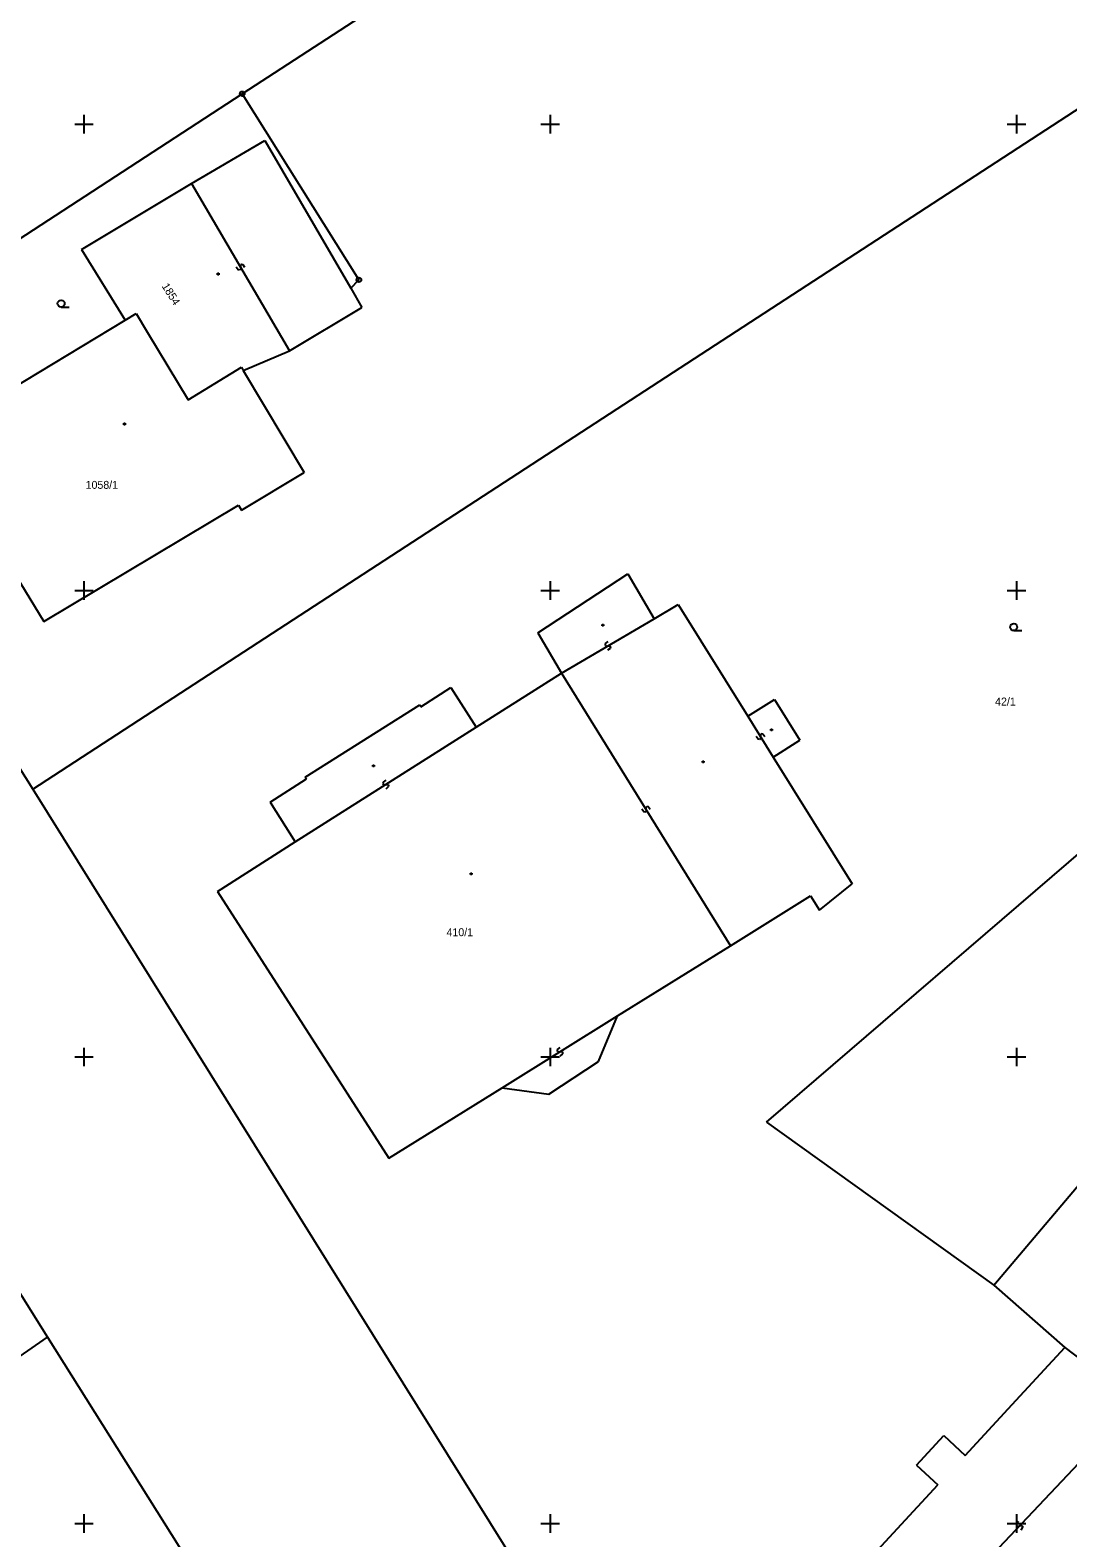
# Model space of a CAD drawing. Extents: x -492811 to -492366, y -1127107 to -1126748.
# Drawn here: x -492702.3 to -492657.8, y -1127040.6 to -1126976 of the extents above; entities that cross this region are included whole.
import ezdxf

# ---------------------------------------------------------------- set-up
doc = ezdxf.new("R2010")
doc.units = 0
doc.layers.add('katastrální mapa', color=7, linetype='Continuous')
doc.layers.add('síť', color=7, linetype='Continuous')

msp = doc.modelspace()

# ---------------------------------------------------------------- linework, layer by layer
at = {"layer": 'katastrální mapa'}
for p, q in [((-492693.21, -1126978.7), (-492665.87, -1126960.94)), ((-492702.2, -1127008.51), (-492653.87, -1126977.07)), ((-492712.9, -1126991.51), (-492693.21, -1126978.7)), ((-492693.21, -1126978.7), (-492688.21, -1126986.68)), ((-492695.39, -1126982.55), (-492692.25, -1126980.7)), ((-492692.25, -1126980.7), (-492688.56, -1126987.04)), ((-492700.1, -1126985.38), (-492695.39, -1126982.55)), ((-492695.39, -1126982.55), (-492691.18, -1126989.73)), ((-492700.1, -1126985.38), (-492698.24, -1126988.41)), ((-492694.28, -1126986.4), (-492694.22, -1126986.4)), ((-492694.28, -1126986.46), (-492694.28, -1126986.4)), ((-492694.22, -1126986.46), (-492694.28, -1126986.46)), ((-492694.22, -1126986.4), (-492694.22, -1126986.46)), ((-492693.39, -1126986.25), (-492693.47, -1126986.13)), ((-492693.33, -1126986.26), (-492693.39, -1126986.25)), ((-492693.3, -1126986.24), (-492693.33, -1126986.26)), ((-492693.28, -1126986.18), (-492693.3, -1126986.24)), ((-492693.27, -1126986.04), (-492693.29, -1126986.1)), ((-492693.29, -1126986.1), (-492693.28, -1126986.18)), ((-492693.24, -1126986.02), (-492693.27, -1126986.04)), ((-492693.18, -1126986.03), (-492693.24, -1126986.02)), ((-492693.1, -1126986.15), (-492693.18, -1126986.03)), ((-492688.56, -1126987.04), (-492688.21, -1126986.68)), ((-492688.56, -1126987.04), (-492688.09, -1126987.86)), ((-492700.98, -1126987.85), (-492700.63, -1126987.85)), ((-492691.18, -1126989.73), (-492688.09, -1126987.86)), ((-492706.55, -1126993.43), (-492698.24, -1126988.41)), ((-492698.24, -1126988.41), (-492697.76, -1126988.13)), ((-492697.76, -1126988.13), (-492697.27, -1126988.94)), ((-492697.27, -1126988.94), (-492695.53, -1126991.82)), ((-492693.17, -1126990.56), (-492691.18, -1126989.73)), ((-492695.53, -1126991.82), (-492693.25, -1126990.43)), ((-492693.25, -1126990.43), (-492693.17, -1126990.56)), ((-492693.17, -1126990.56), (-492690.55, -1126994.94)), ((-492698.29, -1126992.83), (-492698.23, -1126992.83)), ((-492698.29, -1126992.89), (-492698.29, -1126992.83)), ((-492698.23, -1126992.89), (-492698.29, -1126992.89)), ((-492698.23, -1126992.83), (-492698.23, -1126992.89)), ((-492706.55, -1126993.43), (-492701.72, -1127001.33)), ((-492693.24, -1126996.55), (-492690.55, -1126994.94)), ((-492710.29, -1126995.67), (-492702.2, -1127008.51)), ((-492670.72, -1127022.8), (-492639.2, -1126995.68)), ((-492701.72, -1127001.33), (-492693.37, -1126996.34)), ((-492693.37, -1126996.34), (-492693.24, -1126996.55)), ((-492680.53, -1127001.82), (-492676.67, -1126999.29)), ((-492676.67, -1126999.29), (-492675.55, -1127001.21)), ((-492675.55, -1127001.21), (-492674.51, -1127000.6)), ((-492674.51, -1127000.6), (-492671.53, -1127005.39)), ((-492679.52, -1127003.54), (-492675.55, -1127001.21)), ((-492680.53, -1127001.82), (-492679.52, -1127003.54)), ((-492677.78, -1127001.45), (-492677.72, -1127001.45)), ((-492677.78, -1127001.51), (-492677.78, -1127001.45)), ((-492677.72, -1127001.51), (-492677.78, -1127001.51)), ((-492677.72, -1127001.45), (-492677.72, -1127001.51)), ((-492660.12, -1127001.72), (-492659.77, -1127001.72)), ((-492677.64, -1127002.27), (-492677.65, -1127002.33)), ((-492677.65, -1127002.33), (-492677.63, -1127002.36)), ((-492677.53, -1127002.19), (-492677.64, -1127002.27)), ((-492677.63, -1127002.36), (-492677.58, -1127002.38)), ((-492677.58, -1127002.38), (-492677.49, -1127002.37)), ((-492677.43, -1127002.48), (-492677.54, -1127002.56)), ((-492677.49, -1127002.37), (-492677.44, -1127002.39)), ((-492677.44, -1127002.39), (-492677.42, -1127002.42)), ((-492677.42, -1127002.42), (-492677.43, -1127002.48)), ((-492683.18, -1127005.86), (-492679.52, -1127003.54)), ((-492679.52, -1127003.54), (-492672.27, -1127015.23)), ((-492685.55, -1127004.98), (-492684.26, -1127004.16)), ((-492684.26, -1127004.16), (-492683.18, -1127005.86)), ((-492671.53, -1127005.39), (-492670.38, -1127004.67)), ((-492670.38, -1127004.67), (-492669.29, -1127006.42)), ((-492690.51, -1127008), (-492685.6, -1127004.9)), ((-492685.6, -1127004.9), (-492685.55, -1127004.98)), ((-492690.94, -1127010.78), (-492683.18, -1127005.86)), ((-492671.53, -1127005.39), (-492670.44, -1127007.14)), ((-492670.54, -1127005.94), (-492670.48, -1127005.94)), ((-492670.54, -1127006), (-492670.54, -1127005.94)), ((-492670.48, -1127005.94), (-492670.48, -1127006)), ((-492671.08, -1127006.37), (-492671.17, -1127006.26)), ((-492671.03, -1127006.39), (-492671.08, -1127006.37)), ((-492670.99, -1127006.36), (-492671.03, -1127006.39)), ((-492670.98, -1127006.17), (-492670.99, -1127006.22)), ((-492670.99, -1127006.22), (-492670.98, -1127006.31)), ((-492670.98, -1127006.31), (-492670.99, -1127006.36)), ((-492670.94, -1127006.14), (-492670.98, -1127006.17)), ((-492670.89, -1127006.16), (-492670.94, -1127006.14)), ((-492670.8, -1127006.27), (-492670.89, -1127006.16)), ((-492670.48, -1127006), (-492670.54, -1127006)), ((-492670.44, -1127007.14), (-492669.29, -1127006.42)), ((-492670.44, -1127007.14), (-492667.05, -1127012.57)), ((-492687.61, -1127007.49), (-492687.55, -1127007.49)), ((-492687.61, -1127007.55), (-492687.61, -1127007.49)), ((-492687.55, -1127007.55), (-492687.61, -1127007.55)), ((-492687.55, -1127007.49), (-492687.55, -1127007.55)), ((-492673.47, -1127007.32), (-492673.41, -1127007.32)), ((-492673.47, -1127007.38), (-492673.47, -1127007.32)), ((-492673.41, -1127007.38), (-492673.47, -1127007.38)), ((-492673.41, -1127007.32), (-492673.41, -1127007.38)), ((-492702.2, -1127008.51), (-492679.24, -1127045.33)), ((-492692.02, -1127009.08), (-492690.45, -1127008.08)), ((-492690.51, -1127008), (-492690.45, -1127008.08)), ((-492687.17, -1127008.22), (-492687.18, -1127008.28)), ((-492687.18, -1127008.28), (-492687.16, -1127008.31)), ((-492687.06, -1127008.13), (-492687.17, -1127008.22)), ((-492687.16, -1127008.31), (-492687.1, -1127008.32)), ((-492687.1, -1127008.32), (-492687.02, -1127008.32)), ((-492686.95, -1127008.42), (-492687.06, -1127008.51)), ((-492687.02, -1127008.32), (-492686.96, -1127008.33)), ((-492686.96, -1127008.33), (-492686.94, -1127008.36)), ((-492686.94, -1127008.36), (-492686.95, -1127008.42)), ((-492692.02, -1127009.08), (-492690.94, -1127010.78)), ((-492675.99, -1127009.49), (-492676.08, -1127009.38)), ((-492675.94, -1127009.51), (-492675.99, -1127009.49)), ((-492675.9, -1127009.48), (-492675.94, -1127009.51)), ((-492675.89, -1127009.29), (-492675.9, -1127009.34)), ((-492675.9, -1127009.34), (-492675.89, -1127009.43)), ((-492675.89, -1127009.43), (-492675.9, -1127009.48)), ((-492675.85, -1127009.26), (-492675.89, -1127009.29)), ((-492675.8, -1127009.28), (-492675.85, -1127009.26)), ((-492675.71, -1127009.39), (-492675.8, -1127009.28)), ((-492694.28, -1127012.9), (-492690.94, -1127010.78)), ((-492683.42, -1127012.12), (-492683.36, -1127012.12)), ((-492683.42, -1127012.18), (-492683.42, -1127012.12)), ((-492683.36, -1127012.18), (-492683.42, -1127012.18)), ((-492683.36, -1127012.12), (-492683.36, -1127012.18)), ((-492694.28, -1127012.9), (-492686.93, -1127024.34)), ((-492668.45, -1127013.71), (-492667.05, -1127012.57)), ((-492672.27, -1127015.23), (-492668.84, -1127013.09)), ((-492668.84, -1127013.09), (-492668.45, -1127013.71)), ((-492677.11, -1127018.23), (-492672.27, -1127015.23)), ((-492710.85, -1127017.26), (-492701.56, -1127032.01)), ((-492682.07, -1127021.32), (-492677.11, -1127018.23)), ((-492677.93, -1127020.2), (-492677.11, -1127018.23)), ((-492679.7, -1127019.68), (-492679.71, -1127019.73)), ((-492679.71, -1127019.73), (-492679.69, -1127019.77)), ((-492679.59, -1127019.59), (-492679.7, -1127019.68)), ((-492679.69, -1127019.77), (-492679.63, -1127019.78)), ((-492679.63, -1127019.78), (-492679.55, -1127019.77)), ((-492679.48, -1127019.87), (-492679.59, -1127019.96)), ((-492679.55, -1127019.77), (-492679.49, -1127019.78)), ((-492679.49, -1127019.78), (-492679.47, -1127019.82)), ((-492679.47, -1127019.82), (-492679.48, -1127019.87)), ((-492660.97, -1127029.78), (-492652.44, -1127019.69)), ((-492680.06, -1127021.59), (-492677.93, -1127020.2)), ((-492686.93, -1127024.34), (-492682.07, -1127021.32)), ((-492682.07, -1127021.32), (-492680.06, -1127021.59)), ((-492670.72, -1127022.8), (-492660.97, -1127029.78)), ((-492660.97, -1127029.78), (-492657.93, -1127032.45)), ((-492729.49, -1127051.33), (-492701.56, -1127032.01)), ((-492701.56, -1127032.01), (-492683.61, -1127060.59)), ((-492660.19, -1127034.9), (-492657.93, -1127032.45)), ((-492657.93, -1127032.45), (-492654.86, -1127034.8)), ((-492664.88, -1127045.39), (-492654.86, -1127034.8)), ((-492662.21, -1127037.08), (-492660.19, -1127034.9)), ((-492664.29, -1127037.5), (-492663.12, -1127036.23)), ((-492663.12, -1127036.23), (-492662.21, -1127037.08)), ((-492664.29, -1127037.5), (-492663.38, -1127038.34)), ((-492668.32, -1127043.68), (-492663.38, -1127038.34)), ((-492659.92, -1127039.91), (-492660, -1127040.03)), ((-492660, -1127040.03), (-492660, -1127040.08)), ((-492660, -1127040.08), (-492659.97, -1127040.11)), ((-492659.97, -1127040.11), (-492659.91, -1127040.11)), ((-492659.91, -1127040.11), (-492659.83, -1127040.08)), ((-492659.83, -1127040.08), (-492659.77, -1127040.08)), ((-492659.74, -1127040.16), (-492659.82, -1127040.28)), ((-492659.77, -1127040.08), (-492659.74, -1127040.11)), ((-492659.74, -1127040.11), (-492659.74, -1127040.16))]:
    msp.add_line(p, q, dxfattribs=at)
for centre, radius in [((-492693.21, -1126978.7), 0.1), ((-492693.21, -1126978.7), 0.002), ((-492688.21, -1126986.68), 0.1), ((-492688.21, -1126986.68), 0.002), ((-492700.98, -1126987.7), 0.15), ((-492660.12, -1127001.57), 0.15)]:
    msp.add_circle(centre, radius, dxfattribs=at)
at = {"layer": 'síť'}
for p, q in [((-492700.4, -1126980), (-492699.6, -1126980)), ((-492700, -1126979.6), (-492700, -1126980.4)), ((-492680.4, -1126980), (-492679.6, -1126980)), ((-492680, -1126979.6), (-492680, -1126980.4)), ((-492660.4, -1126980), (-492659.6, -1126980)), ((-492660, -1126979.6), (-492660, -1126980.4)), ((-492700.4, -1127000), (-492699.6, -1127000)), ((-492700, -1126999.6), (-492700, -1127000.4)), ((-492680.4, -1127000), (-492679.6, -1127000)), ((-492680, -1126999.6), (-492680, -1127000.4)), ((-492660.4, -1127000), (-492659.6, -1127000)), ((-492660, -1126999.6), (-492660, -1127000.4)), ((-492700.4, -1127020), (-492699.6, -1127020)), ((-492700, -1127019.6), (-492700, -1127020.4)), ((-492680.4, -1127020), (-492679.6, -1127020)), ((-492680, -1127019.6), (-492680, -1127020.4)), ((-492660.4, -1127020), (-492659.6, -1127020)), ((-492660, -1127019.6), (-492660, -1127020.4)), ((-492700.4, -1127040), (-492699.6, -1127040)), ((-492700, -1127039.6), (-492700, -1127040.4)), ((-492680.4, -1127040), (-492679.6, -1127040)), ((-492680, -1127039.6), (-492680, -1127040.4)), ((-492660.4, -1127040), (-492659.6, -1127040)), ((-492660, -1127039.6), (-492660, -1127040.4))]:
    msp.add_line(p, q, dxfattribs=at)

# ---------------------------------------------------------------- texts
at = {"layer": 'katastrální mapa'}
msp.add_text('1854', height=0.34, rotation=302.175, dxfattribs=at).set_placement((-492696.68, -1126986.95))
for s, p in [('1058/1', (-492699.93, -1126995.64)), ('42/1', (-492660.92, -1127004.93)), ('410/1', (-492684.45, -1127014.82))]:
    msp.add_text(s, height=0.34, dxfattribs=at).set_placement(p)

doc.saveas('drawing.dxf')
